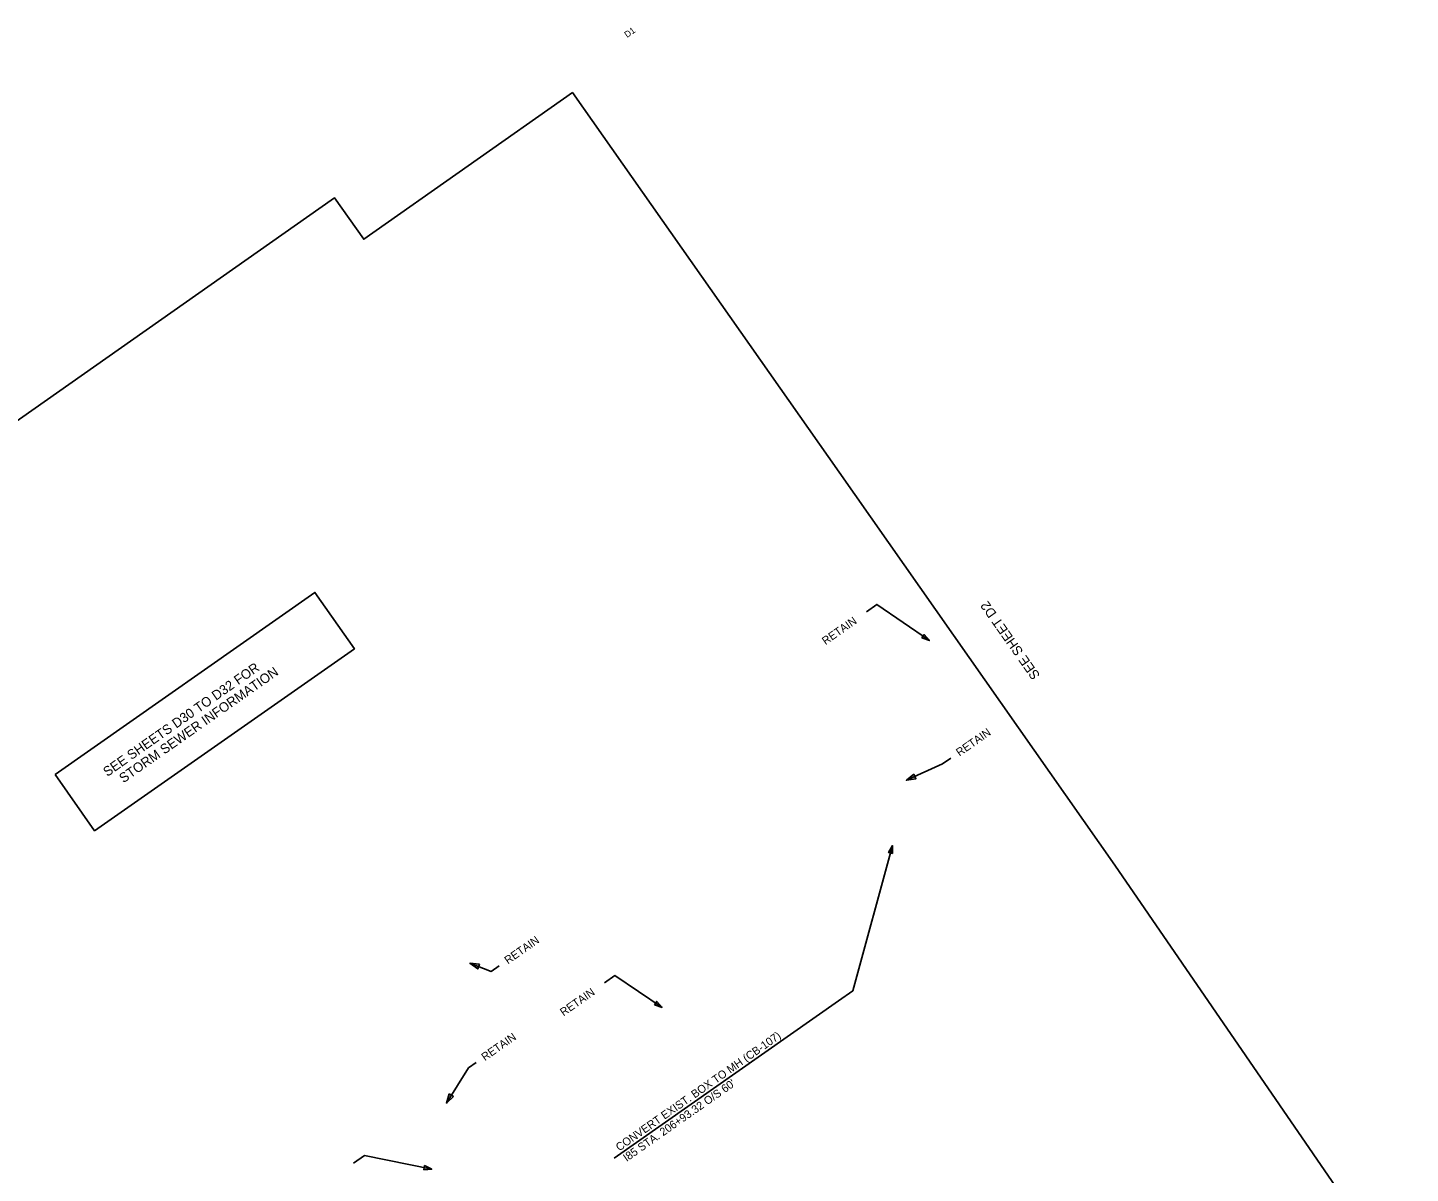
# Model space of a CAD drawing. Extents: x 1602342 to 1604404, y 1087462 to 1090274.
# Drawn here: x 1603498 to 1604362, y 1088812 to 1089528 of the extents above; entities that cross this region are included whole.
import ezdxf

# ---------------------------------------------------------------- set-up
doc = ezdxf.new("R2010")
doc.units = 0
for name, color, linetype in [('Plan_Clip', 7, 'Continuous'), ('RD_SHT_Bndy', 7, 'Continuous'), ('RD_SHT_MatchLine', 7, 'Continuous'), ('RD_TX_Drainage', 7, 'Continuous')]:
    doc.layers.add(name, color=color, linetype=linetype)

msp = doc.modelspace()

# ---------------------------------------------------------------- linework, layer by layer
at = {"layer": 'Plan_Clip'}
msp.add_lwpolyline([(1604005.53, 1089249.68), (1604177.81, 1089004.07), (1604362.43, 1088735.18), (1603082.39, 1087856.27), (1602843.15, 1088301.48), (1602638.5, 1088682.3), (1603690.27, 1089421.2), (1603708.44, 1089395.33), (1603838.88, 1089486.97)], close=True, dxfattribs=at)
msp.add_lwpolyline([(1604005.53, 1089249.68), (1604177.81, 1089004.07), (1604362.43, 1088735.18), (1603082.39, 1087856.27), (1602843.15, 1088301.48), (1602638.5, 1088682.3), (1603690.27, 1089421.2), (1603708.44, 1089395.33), (1603838.88, 1089486.97)], close=True, dxfattribs=at)
msp.add_lwpolyline([(1604005.53, 1089249.68), (1604177.81, 1089004.07), (1604362.43, 1088735.18), (1603082.39, 1087856.27), (1602843.15, 1088301.48), (1602638.5, 1088682.3), (1603690.27, 1089421.2), (1603708.44, 1089395.33), (1603838.88, 1089486.97)], close=True, dxfattribs=at)
msp.add_lwpolyline([(1604005.53, 1089249.68), (1604177.81, 1089004.07), (1604362.43, 1088735.18), (1603082.39, 1087856.27), (1602843.15, 1088301.48), (1602638.5, 1088682.3), (1603690.27, 1089421.2), (1603708.44, 1089395.33), (1603838.88, 1089486.97)], close=True, dxfattribs=at)
msp.add_lwpolyline([(1604005.53, 1089249.68), (1604177.81, 1089004.07), (1604362.43, 1088735.18), (1603082.39, 1087856.27), (1602843.15, 1088301.48), (1602638.5, 1088682.3), (1603690.27, 1089421.2), (1603708.44, 1089395.33), (1603838.88, 1089486.97)], close=True, dxfattribs=at)
at = {"layer": 'RD_TX_Drainage'}
msp.add_line((1604005.06, 1088919.39), (1603864.89, 1088821.07), dxfattribs=at)
for points in [[(1603515.67, 1089060.74), (1603677.93, 1089174.56), (1603702.57, 1089139.43), (1603540.3, 1089025.62)], [(1604057.18, 1089146.17), (1604061.89, 1089144.49), (1604058.65, 1089148.3)], [(1604052.19, 1089061.02), (1604047.57, 1089057.19), (1604053.49, 1089058.2)], [(1604038.85, 1089011.37), (1604038.88, 1089016.37), (1604036.35, 1089012.05)], [(1603780.76, 1088942.19), (1603774.79, 1088942.83), (1603779.64, 1088939.29)], [(1603890.11, 1088916.85), (1603894.84, 1088915.22), (1603891.56, 1088918.99)], [(1603761.87, 1088861.13), (1603760.11, 1088855.4), (1603764.5, 1088859.49)], [(1603745.89, 1088813.81), (1603750.89, 1088814.12), (1603746.41, 1088816.35)]]:
    msp.add_lwpolyline(points, close=True, dxfattribs=at)
for points in [[(1604022.53, 1089162.57), (1604029.06, 1089167.15), (1604061.89, 1089144.49)], [(1604075.21, 1089071.12), (1604070.12, 1089067.54), (1604047.57, 1089057.19)], [(1604005.06, 1088919.39), (1604013.98, 1088925.65), (1604038.88, 1089016.37)], [(1603793.02, 1088941.22), (1603788.04, 1088937.73), (1603774.79, 1088942.83)], [(1603858.82, 1088930.55), (1603865.35, 1088935.13), (1603894.84, 1088915.22)], [(1603778.63, 1088880.76), (1603773.93, 1088877.46), (1603760.11, 1088855.4)], [(1603702.08, 1088817.93), (1603708.85, 1088822.68), (1603750.89, 1088814.12)]]:
    msp.add_lwpolyline(points, dxfattribs=at)

# ---------------------------------------------------------------- texts
at = {"layer": 'RD_SHT_Bndy'}
msp.add_text('D1', height=4, rotation=35.04683, dxfattribs=at).set_placement((1603873.02, 1089521.04))
at = {"layer": 'RD_SHT_MatchLine'}
msp.add_text('SEE SHEET D2', height=6, rotation=125.0981, dxfattribs=at).set_placement((1604131.34, 1089122.74))
at = {"layer": 'RD_TX_Drainage'}
for s, height, p in [('RETAIN', 5, (1603996.99, 1089141.6)), ('SEE SHEETS D30 TO D32 FOR', 6, (1603548.23, 1089059.21)), ('STORM SEWER INFORMATION', 6, (1603558.27, 1089055.26)), ('RETAIN', 5, (1604080.74, 1089071.94)), ('RETAIN', 5, (1603798.55, 1088942.05)), ('RETAIN', 5, (1603833.28, 1088909.58)), ('RETAIN', 5, (1603784.16, 1088881.58)), ('CONVERT EXIST. BOX TO MH (CB-107)', 5, (1603868.12, 1088825.17)), ("I85 STA. 206+93.32 O/S 60'", 5, (1603872.71, 1088818.62))]:
    msp.add_text(s, height=height, rotation=35.04683, dxfattribs=at).set_placement(p)

doc.saveas('drawing.dxf')
